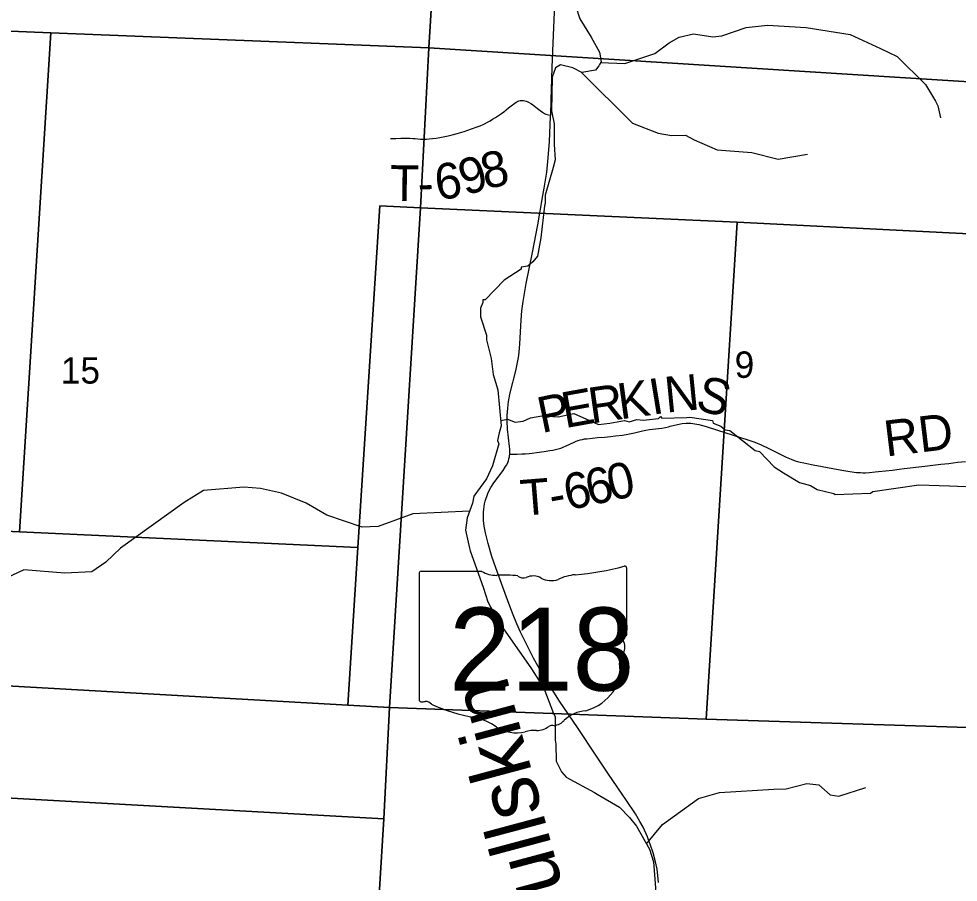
# Model space of a CAD drawing. Extents: x 396.2 to 468.4, y 232.6 to 279.1.
# Drawn here: x 418.928 to 420.419, y 272.044 to 273.414 of the extents above; entities that cross this region are included whole.
import ezdxf

# ---------------------------------------------------------------- set-up
doc = ezdxf.new("R2010")
doc.units = 0
for name, color, linetype in [('GM_X_Minor_River', 7, 'Continuous'), ('GM_X_Minor_River_Text', 7, 'Continuous'), ('GM_X_Section', 7, 'Continuous'), ('GM_X_Section_Text', 7, 'Continuous'), ('GM_X_State_Location', 7, 'Continuous'), ('GM_X_State_Route', 7, 'Continuous'), ('GM_X_State_Shield', 7, 'Continuous'), ('GM_X_Township_Road', 7, 'Continuous'), ('GM_X_Township_Road_Text', 7, 'Continuous')]:
    doc.layers.add(name, color=color, linetype=linetype)

msp = doc.modelspace()

# ---------------------------------------------------------------- linework, layer by layer
at = {"layer": 'GM_X_Minor_River'}
for points in [[(419.8117, 273.4355), (419.8185, 273.4142), (419.8363, 273.385), (419.8499, 273.3615), (419.8522, 273.3459), (419.8496, 273.3417), (419.8485, 273.3394), (419.8432, 273.3326), (419.8216, 273.3291), (419.8076, 273.3363), (419.7876, 273.3412), (419.7797, 273.3366), (419.7748, 273.3218), (419.7733, 273.2682), (419.7779, 273.2477), (419.7779, 273.215), (419.7794, 273.1903), (419.7764, 273.1781), (419.7632, 273.1344), (419.7636, 273.1211), (419.7625, 273.1172), (419.7565, 273.0667), (419.7512, 273.0378), (419.7437, 273.0286), (419.7361, 273.0218), (419.7255, 273.0199), (419.7252, 273.0168), (419.6983, 272.9996), (419.6681, 272.9684), (419.6647, 272.968), (419.6647, 272.9638), (419.6609, 272.9551), (419.6606, 272.9414), (419.6704, 272.9122), (419.6701, 272.9049), (419.678, 272.8749), (419.6807, 272.8498), (419.6883, 272.8255), (419.6936, 272.7685), (419.6902, 272.7571), (419.688, 272.7449), (419.6899, 272.7396), (419.6797, 272.705), (419.6703, 272.6841), (419.6503, 272.6567)], [(419.8511, 273.3448), (419.89, 273.3435), (419.9377, 273.3591), (419.9605, 273.3762), (419.9759, 273.3852), (419.9988, 273.3906), (420.0296, 273.3858), (420.0437, 273.3872), (420.0826, 273.4004), (420.1164, 273.4043), (420.1779, 273.4004), (420.2478, 273.3891), (420.2956, 273.3674), (420.3224, 273.3544), (420.3671, 273.3101), (420.383, 273.2837), (420.3869, 273.276), (420.3909, 273.2573)], [(419.8204, 273.3297), (419.9019, 273.2487), (419.943, 273.2326), (419.9641, 273.2289), (419.986, 273.2297), (420.0002, 273.222), (420.0367, 273.2064), (420.0914, 273.202), (420.1334, 273.1916), (420.1798, 273.1992)], [(419.6929, 272.7769), (419.7035, 272.7788), (419.7159, 272.7739), (419.7284, 272.7754), (419.7401, 272.7808), (419.7583, 272.7839), (419.784, 272.7824), (419.8089, 272.7878), (419.8479, 272.7704), (419.866, 272.7724), (419.8894, 272.7766), (419.897, 272.7747), (419.9091, 272.7785), (419.9197, 272.7774), (419.9435, 272.7801), (419.9465, 272.7828), (419.9484, 272.7805), (419.9885, 272.7814), (419.993, 272.7818), (420.0289, 272.7765), (420.0301, 272.7724), (420.0422, 272.7678), (420.049, 272.7618), (420.0565, 272.7606), (420.097, 272.7292), (420.1035, 272.7273), (420.1269, 272.703), (420.142, 272.6935), (420.167, 272.6784), (420.1844, 272.6735), (420.1954, 272.6671), (420.2215, 272.6607), (420.2237, 272.6591), (420.2797, 272.6612), (420.2835, 272.6638), (420.3568, 272.6747), (420.4055, 272.6729), (420.4566, 272.6711)], [(419.6436, 272.633), (419.5536, 272.6285), (419.4983, 272.6084), (419.4732, 272.6076), (419.417, 272.6263), (419.3842, 272.6455), (419.345, 272.6612), (419.3116, 272.669), (419.285, 272.6711), (419.2213, 272.6655), (419.1903, 272.6467), (419.0894, 272.5741), (419.066, 272.5519), (419.0437, 272.5366), (419.0008, 272.5345), (418.9359, 272.5395), (418.8792, 272.5133), (418.8686, 272.5083), (418.8667, 272.508)], [(419.6503, 272.6567), (419.648, 272.6456), (419.6397, 272.6221), (419.6371, 272.6027), (419.6432, 272.5742), (419.6443, 272.57), (419.6652, 272.5123), (419.6724, 272.4887), (419.689, 272.4583), (419.7416, 272.3828), (419.7613, 272.3521), (419.7765, 272.3118), (419.7791, 272.3069), (419.7792, 272.2692), (419.7804, 272.2628)], [(419.7804, 272.2631), (419.7807, 272.2362), (419.7894, 272.2191), (419.797, 272.2107), (419.8416, 272.1865), (419.8458, 272.1839), (419.8814, 272.163), (419.8973, 272.1467), (419.9086, 272.1327), (419.9291, 272.0962), (419.9355, 272.0761), (419.9397, 272.021)], [(419.9242, 272.1048), (419.9497, 272.1355), (420.0069, 272.177), (420.0401, 272.1862), (420.1264, 272.1914), (420.1461, 272.1923), (420.1789, 272.2004), (420.1977, 272.1983), (420.2157, 272.1825), (420.2297, 272.1805), (420.2724, 272.194)]]:
    msp.add_lwpolyline(points, dxfattribs=at)
at = {"layer": 'GM_X_Section'}
for points in [[(418.6011, 274.4105), (419.6431, 274.3525), (419.617, 273.9581), (419.5894, 273.5404), (419.5789, 273.368), (418.9789, 273.3919), (418.5411, 273.4101), (418.5524, 273.5824), (418.5769, 274)], [(419.5894, 273.5404), (420.6398, 273.4786), (420.6297, 273.3021), (419.5789, 273.368)], [(418.9789, 273.3919), (418.9289, 272.6001), (418.4866, 272.6208), (418.5234, 273.1631), (418.5411, 273.4101)], [(419.5789, 273.368), (419.5657, 273.1142), (419.5009, 273.1172), (419.4663, 272.575), (418.9289, 272.6001), (418.9789, 273.3919)], [(420.6297, 273.3021), (420.6294, 273.296), (420.6152, 273.0642), (420.0684, 273.0913), (419.5657, 273.1142), (419.5789, 273.368)], [(419.5657, 273.1142), (419.5162, 272.3211), (419.4504, 272.3249), (419.4663, 272.575), (419.5009, 273.1172)], [(420.0684, 273.0913), (420.0191, 272.3027), (419.5162, 272.3211), (419.5657, 273.1142)], [(420.6152, 273.0642), (420.5671, 272.2854), (420.0191, 272.3027), (420.0684, 273.0913)], [(418.9289, 272.6001), (419.4663, 272.575), (419.4504, 272.3249), (418.4704, 272.3805), (418.4866, 272.6208)], [(419.4504, 272.3249), (419.5162, 272.3211), (419.5072, 272.1445), (418.4583, 272.2026), (418.4704, 272.3805)], [(419.5162, 272.3211), (420.0191, 272.3027), (420.5671, 272.2854), (420.4987, 271.28), (419.4571, 271.3312), (419.4827, 271.7399), (419.5072, 272.1445)], [(419.5072, 272.1445), (419.4827, 271.7399), (418.4305, 271.792), (418.4583, 272.2026)]]:
    msp.add_lwpolyline(points, close=True, dxfattribs=at)
at = {"layer": 'GM_X_State_Route'}
for points in [[(419.76, 273.1338), (419.762, 273.1455), (419.7659, 273.1707), (419.7683, 273.1934), (419.7701, 273.2195), (419.7721, 273.2594), (419.7722, 273.2614), (419.7731, 273.2854), (419.7746, 273.3371), (419.7756, 273.3634), (419.7793, 273.4503)], [(419.9434, 272.0433), (419.9424, 272.0544), (419.9411, 272.0645), (419.9387, 272.0761), (419.9348, 272.0906), (419.9302, 272.1042), (419.9277, 272.1109), (419.9258, 272.1157), (419.9189, 272.1311), (419.9139, 272.1404), (419.907, 272.1522), (419.8927, 272.1738), (419.8642, 272.2156), (419.845, 272.2437), (419.8146, 272.2892), (419.7864, 272.3312), (419.7718, 272.3538), (419.7564, 272.3789), (419.7451, 272.3994), (419.7352, 272.4185), (419.7245, 272.4408), (419.7187, 272.4538), (419.7126, 272.4685), (419.7056, 272.4864), (419.696, 272.512), (419.685, 272.5428), (419.6788, 272.5606), (419.6728, 272.5815), (419.6688, 272.5982), (419.6668, 272.6089), (419.6657, 272.6178), (419.6654, 272.6245), (419.6655, 272.6313), (419.666, 272.6361), (419.6665, 272.6404), (419.6672, 272.6445), (419.6681, 272.6488), (419.6696, 272.6535), (419.6706, 272.6563), (419.6731, 272.6625), (419.6773, 272.6704), (419.682, 272.6776), (419.6969, 272.6975), (419.7007, 272.7035), (419.7024, 272.7065), (419.7041, 272.7101), (419.7052, 272.7129), (419.706, 272.7158), (419.7066, 272.7188), (419.7071, 272.7212), (419.7073, 272.7235), (419.7074, 272.7274), (419.7072, 272.7314), (419.7069, 272.7352), (419.7039, 272.7628), (419.7029, 272.7764), (419.703, 272.7844), (419.704, 272.7961), (419.7055, 272.8071), (419.7081, 272.8205), (419.7167, 272.8554), (419.7206, 272.874), (419.7216, 272.8801), (419.7223, 272.8855), (419.7235, 272.8979), (419.7252, 272.9364), (419.7263, 272.9506), (419.7283, 272.9654), (419.7335, 272.9941), (419.7434, 273.0432), (419.7519, 273.0873), (419.76, 273.1338)]]:
    msp.add_lwpolyline(points, dxfattribs=at)
at = {"layer": 'GM_X_State_Shield'}
for p, q in [((419.6631, 272.5373), (419.5665, 272.5373)), ((419.8929, 272.4376), (419.8929, 272.5423)), ((419.5633, 272.5339), (419.5633, 272.3337)), ((419.8928, 272.4376), (419.8929, 272.4376))]:
    msp.add_line(p, q, dxfattribs=at)
for centre, major_axis, start_param, end_param in [((419.5671, 272.5343), (0.00382, 0), 1.712693, 3.28349), ((419.686, 272.5605), (0.037, 0), 4.042523, 4.731795), ((419.7755, 272.8101), (0.3495, 0), 4.814394, 5.042369), ((419.8892, 272.5427), (0.00367, 0), 6.141152, 7.989035), ((419.6983, 272.425), (0.133, 0), 1.404758, 1.657858), ((419.7285, 272.5353), (0.0107, 0), 3.836095, 5.185415), ((419.7442, 272.5122), (0.0222, 0), 0.950623, 2.079405), ((419.7729, 272.5439), (0.0267, 0), 4.081561, 5.145723), ((419.82, 272.4762), (0.0703, 0), 1.699011, 2.107814), ((419.892, 272.4299), (0.00568, 0), 1.883978, 3.671073), ((419.889, 272.4372), (0.00393, 0), 5.05454, 6.418171), ((419.8559, 272.4167), (0.0341, 0), 5.934695, 6.695948), ((419.906, 272.3938), (0.0248, 0), 2.387724, 3.262537), ((419.795, 272.3805), (0.0874, 0), 5.101752, 6.440018), ((419.5671, 272.3333), (0.00385, 0), 3.00124, 4.508301), ((419.5677, 272.3538), (0.0294, 0), 4.665946, 4.897461), ((419.5737, 272.3222), (0.0106, 0), 0.519207, 1.627899), ((419.7075, 272.502), (0.2524, 0), 4.195997, 4.488961), ((419.8319, 272.2776), (0.0479, 0), 1.647645, 2.488434), ((419.6323, 272.2438), (0.079, 0), 0.823519, 1.323587), ((419.7712, 272.3143), (0.0282, 0), 4.937069, 5.64225), ((419.7177, 272.3212), (0.0501, 0), 4.026481, 4.996735), ((419.7466, 272.252), (0.0412, 0), 1.495662, 1.94098), ((419.7503, 272.3062), (0.0267, 0), 4.691044, 5.507374), ((419.7744, 272.2868), (0.00752, 0), 1.147584, 2.315152)]:
    msp.add_ellipse(centre, major_axis=major_axis, ratio=0.8, start_param=start_param, end_param=end_param, dxfattribs=at)
at = {"layer": 'GM_X_Township_Road'}
for points in [[(419.5178, 273.2241), (419.5265, 273.2243), (419.5346, 273.2246), (419.5424, 273.2247), (419.5486, 273.2246), (419.5533, 273.2245), (419.5573, 273.2242), (419.5613, 273.2238), (419.5655, 273.2235), (419.5706, 273.2234), (419.575, 273.2235), (419.5791, 273.2237), (419.5844, 273.2241), (419.5902, 273.2248), (419.596, 273.2257), (419.6017, 273.2268), (419.6093, 273.2283), (419.6158, 273.2299), (419.6236, 273.2321), (419.6348, 273.2356), (419.6467, 273.2396), (419.6553, 273.2426), (419.6603, 273.2445), (419.6648, 273.2465), (419.6681, 273.248), (419.672, 273.25), (419.676, 273.2523), (419.68, 273.2548), (419.6846, 273.2577), (419.6908, 273.2618), (419.6943, 273.2642), (419.6978, 273.2668), (419.7055, 273.273), (419.7093, 273.2761), (419.7152, 273.2806), (419.7174, 273.2819), (419.7197, 273.2831), (419.7217, 273.2839), (419.7236, 273.2844), (419.7252, 273.2847), (419.727, 273.2848), (419.7291, 273.2846), (419.7313, 273.2842), (419.7332, 273.2837), (419.7351, 273.2829), (419.7372, 273.2819), (419.7409, 273.2798), (419.7435, 273.2781), (419.746, 273.2763), (419.7513, 273.272), (419.7532, 273.2705), (419.7556, 273.2685), (419.759, 273.2659), (419.7606, 273.2649), (419.7622, 273.264), (419.7643, 273.2631), (419.7665, 273.2624), (419.7687, 273.262), (419.7722, 273.2614)], [(419.7073, 272.7235), (419.7118, 272.7233), (419.7189, 272.7234), (419.7262, 272.7237), (419.7319, 272.7239), (419.7379, 272.7244), (419.7427, 272.7249), (419.7495, 272.7258), (419.7618, 272.7276), (419.7708, 272.729), (419.7755, 272.7298), (419.7801, 272.7307), (419.7842, 272.7317), (419.7882, 272.7329), (419.7921, 272.7344), (419.7968, 272.7364), (419.8097, 272.7424), (419.8128, 272.7438), (419.8158, 272.7448), (419.819, 272.7458), (419.8226, 272.7467), (419.8259, 272.7474), (419.8294, 272.7478), (419.8388, 272.7487), (419.8467, 272.7495), (419.8576, 272.7504), (419.8669, 272.7513), (419.8752, 272.7522), (419.8861, 272.7536), (419.8949, 272.7552), (419.905, 272.7574), (419.9115, 272.7588), (419.9182, 272.7603), (419.923, 272.7612), (419.9292, 272.7623), (419.9434, 272.764), (419.9489, 272.7646), (419.9543, 272.7655), (419.9592, 272.7666), (419.9621, 272.7675), (419.9735, 272.7705), (419.9809, 272.7718), (419.9871, 272.7723), (419.991, 272.7724), (419.9947, 272.7723), (420.0009, 272.7716), (420.0076, 272.7702), (420.019, 272.767), (420.0368, 272.7615), (420.0854, 272.7462), (420.0962, 272.7425), (420.1063, 272.7383), (420.1185, 272.7325), (420.1345, 272.7244), (420.1461, 272.7187), (420.154, 272.7152), (420.1605, 272.7127), (420.1641, 272.7116), (420.1681, 272.7106), (420.1739, 272.7093), (420.1786, 272.7083), (420.189, 272.7063), (420.2029, 272.7038), (420.22, 272.7004), (420.2346, 272.6979), (420.2468, 272.6958), (420.2578, 272.6944), (420.2642, 272.694), (420.2676, 272.6938), (420.2717, 272.6939), (420.2784, 272.6943), (420.2871, 272.695), (420.2926, 272.6956), (420.3148, 272.6981), (420.3253, 272.6993), (420.3333, 272.7003), (420.366, 272.7041), (420.3913, 272.7072), (420.404, 272.7087)], [(420.404, 272.7087), (420.4178, 272.7104), (420.4306, 272.7118)]]:
    msp.add_lwpolyline(points, dxfattribs=at)

# ---------------------------------------------------------------- texts
at = {"layer": 'GM_X_Minor_River_Text'}
msp.add_text('Bullskin', height=0.09471, rotation=105.0011, dxfattribs=at).set_placement((419.8142, 271.9531))
at = {"layer": 'GM_X_Section_Text'}
for s, height, p in [('9', 0.0419, (420.0642, 272.8444)), ('15', 0.04186, (418.9946, 272.8353))]:
    msp.add_text(s, height=height, rotation=0, dxfattribs=at).set_placement(p)
at = {"layer": 'GM_X_State_Location'}
for s in ['s', 'r']:
    msp.add_text(s, height=0.000189, dxfattribs=at).set_placement((419.7244, 272.4205))
msp.add_text('218', height=0.000189, rotation=0, dxfattribs=at).set_placement((419.6575, 272.4067))
at = {"layer": 'GM_X_State_Shield'}
msp.add_text('218', height=0.13184, dxfattribs=at).set_placement((419.6109, 272.3479))
at = {"layer": 'GM_X_Township_Road_Text'}
for s, height, rotation, p in [('9', 0.0568, 17.1355, (419.6364, 273.1332)), ('8', 0.0568, 13.135, (419.6688, 273.1432)), ('T', 0.0568, 359.1664, (419.5168, 273.1253)), ('6', 0.0568, 8.491, (419.5926, 273.126)), ('-', 0.0568, 1.4176, (419.5617, 273.1247)), ('N', 0.0568, 5.6243, (419.9556, 272.7891)), ('K', 0.0568, 7.8733, (419.8824, 272.7784)), ('I', 0.0568, 9.3449, (419.9335, 272.7855)), ('S', 0.0568, 345.3323, (420.0001, 272.7945)), ('E', 0.0568, 10.1916, (419.795, 272.7644)), ('R', 0.0568, 8.1475, (419.8363, 272.7718)), ('P', 0.0568, 11.7297, (419.7579, 272.7566)), ('RD', 0.05682, 6.8826, (420.3047, 272.7194)), ('6', 0.0568, 12.3763, (419.8341, 272.6413)), ('0', 0.0568, 12.4732, (419.8684, 272.6488)), ('6', 0.0568, 11.9572, (419.7994, 272.6339)), ('T', 0.0568, 4.5907, (419.7262, 272.6254)), ('-', 0.0568, 9.9309, (419.7743, 272.6295))]:
    msp.add_text(s, height=height, rotation=rotation, dxfattribs=at).set_placement(p)

doc.saveas('drawing.dxf')
